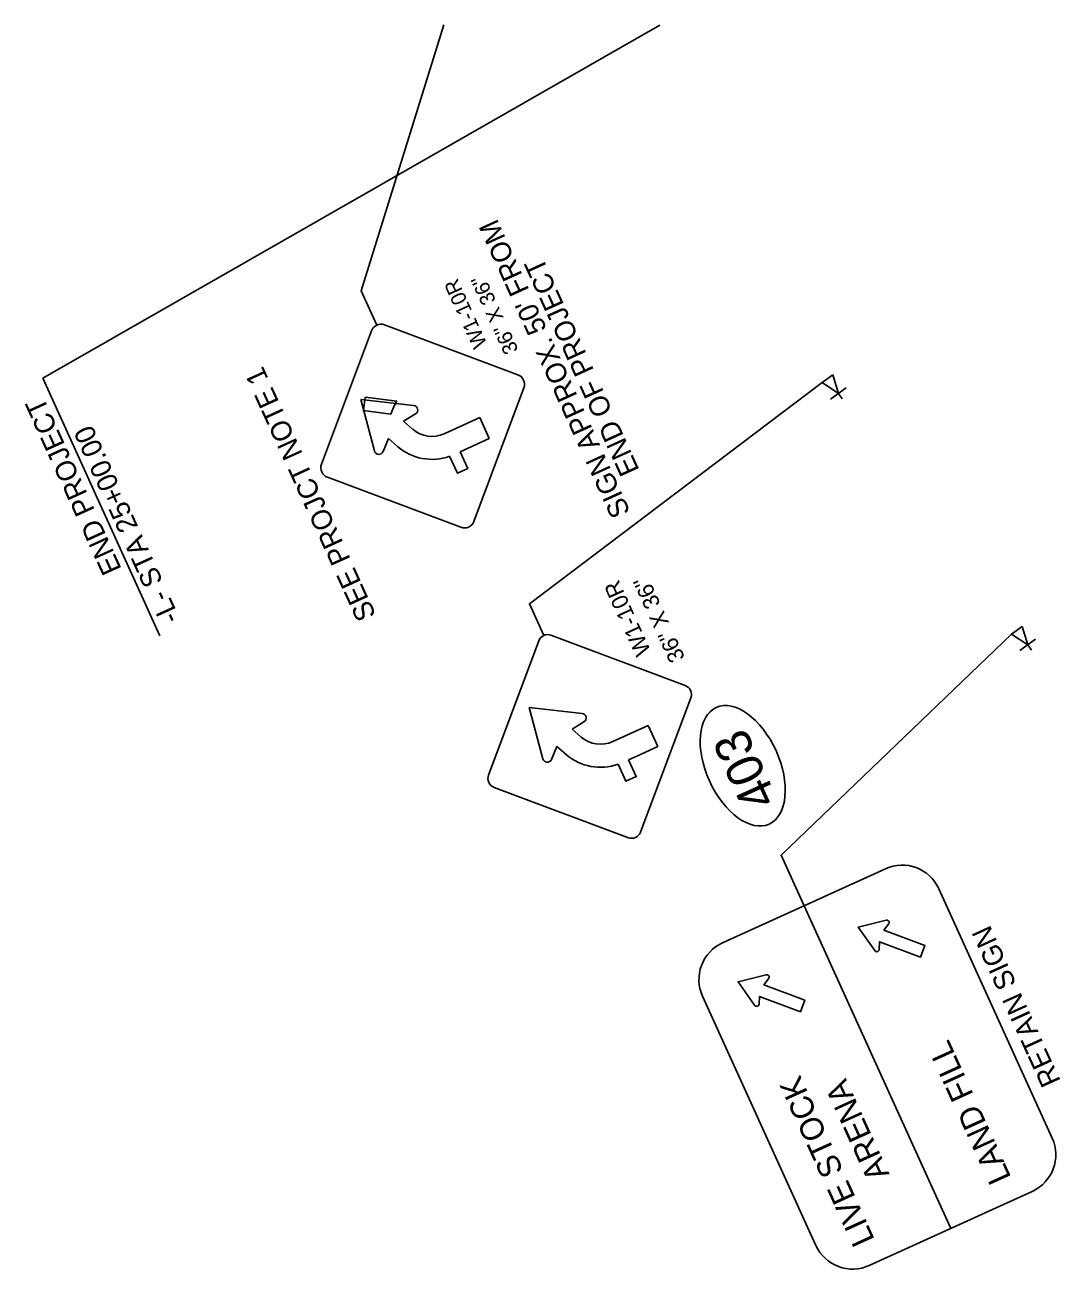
# Model space of a CAD drawing. Extents: x 2096093 to 2099001, y 683546 to 685907.
# Drawn here: x 2096092.8 to 2096451.4, y 684545 to 684975.9 of the extents above; entities that cross this region are included whole.
import ezdxf

# ---------------------------------------------------------------- set-up
doc = ezdxf.new("R2010")
doc.units = 0
for name, color, linetype in [('Default', 7, 'Continuous'), ('Exist Sign E Adopt a Highway CELL', 7, 'Continuous'), ('Exist Sign E Curve Left CELL', 7, 'Continuous'), ('Exist Sign F Left_Right Arrow CELL', 7, 'Continuous'), ('Prop DSN Text', 7, 'Continuous'), ('Prop Horizontal Alignment Station Label', 7, 'Continuous')]:
    doc.layers.add(name, color=color, linetype=linetype)

msp = doc.modelspace()

# ---------------------------------------------------------------- linework, layer by layer
at = {"layer": 'Default'}
for p, q in [((2096368.99, 684851.97), (2096372.7, 684854.63)), ((2096372.7, 684854.63), (2096374.61, 684848.25)), ((2096374.61, 684848.25), (2096368.99, 684851.97)), ((2096371.82, 684846.25), (2096377.35, 684850.22)), ((2096374.61, 684848.25), (2096375.96, 684846.37)), ((2096434.57, 684764.88), (2096438.28, 684767.54)), ((2096440.19, 684761.16), (2096434.57, 684764.88)), ((2096438.28, 684767.54), (2096440.19, 684761.16)), ((2096437.4, 684759.17), (2096442.93, 684763.13)), ((2096440.19, 684761.16), (2096441.54, 684759.28)), ((2096362.69, 684670.78), (2096354.72, 684688.29))]:
    msp.add_line(p, q, dxfattribs=at)
for points in [[(2096214.69, 684871.9), (2096209.27, 684883.81), (2096237.88, 684975.88)], [(2096272.53, 684764.39), (2096267.54, 684775.38), (2096368.99, 684851.97)], [(2096354.72, 684688.29), (2096354.72, 684688.29), (2096434.57, 684764.88)]]:
    msp.add_lwpolyline(points, dxfattribs=at)
msp.add_ellipse((2096341.46, 684719.27), major_axis=(9.17, -20.19), ratio=0.571429, dxfattribs=at)
at = {"layer": 'Exist Sign E Adopt a Highway CELL'}
msp.add_line((2096413.51, 684559.04), (2096362.69, 684670.78), dxfattribs=at)
for points in [[(2096334.45, 684657.94), (2096390.92, 684683.63)], [(2096409.37, 684676.71), (2096448.66, 684590.34)], [(2096366.83, 684553.12), (2096327.54, 684639.49)], [(2096441.74, 684571.89), (2096385.28, 684546.2)]]:
    msp.add_lwpolyline(points, dxfattribs=at)
for centre, start, end in [((2096396.69, 684670.95), 24.458, 114.458), ((2096340.22, 684645.26), 114.458, 204.458), ((2096435.98, 684584.57), 294.458, 24.458), ((2096379.51, 684558.88), 204.458, 294.458)]:
    msp.add_arc(centre, 13.93, start, end, dxfattribs=at)
at = {"layer": 'Exist Sign E Curve Left CELL'}
for p, q in [((2096263.59, 684854.68), (2096217.38, 684871.99)), ((2096212.85, 684869.93), (2096195.53, 684823.72)), ((2096248.33, 684803.93), (2096265.65, 684850.15)), ((2096209.11, 684846.15), (2096227.46, 684844.07)), ((2096213.86, 684828.32), (2096209.11, 684846.15)), ((2096227.46, 684844.07), (2096209.11, 684846.15)), ((2096209.11, 684846.15), (2096213.86, 684828.32)), ((2096227.46, 684844.07), (2096209.11, 684846.15)), ((2096209.11, 684846.15), (2096213.86, 684828.32)), ((2096228.11, 684841.13), (2096223.96, 684838.61)), ((2096223.96, 684838.61), (2096228.11, 684841.13)), ((2096223.96, 684838.61), (2096228.11, 684841.13)), ((2096223.96, 684838.61), (2096227.12, 684835.86)), ((2096227.12, 684835.86), (2096223.96, 684838.61)), ((2096227.12, 684835.86), (2096223.96, 684838.61)), ((2096238.08, 684834.29), (2096250.35, 684839.88)), ((2096250.35, 684839.88), (2096238.08, 684834.29)), ((2096250.35, 684839.88), (2096238.08, 684834.29)), ((2096250.35, 684839.88), (2096253.65, 684832.62)), ((2096253.65, 684832.62), (2096250.35, 684839.88)), ((2096253.65, 684832.62), (2096250.35, 684839.88)), ((2096216.85, 684828.1), (2096218.75, 684832.58)), ((2096218.75, 684832.58), (2096221.91, 684829.83)), ((2096246.37, 684829.3), (2096243.54, 684828.02)), ((2096243.54, 684828.02), (2096246.37, 684829.3)), ((2096243.54, 684828.02), (2096246.37, 684829.3)), ((2096253.65, 684832.62), (2096246.37, 684829.3)), ((2096246.37, 684829.3), (2096253.65, 684832.62)), ((2096246.37, 684829.3), (2096253.65, 684832.62)), ((2096213.86, 684828.32), (2096213.85, 684828.31)), ((2096213.86, 684828.32), (2096213.85, 684828.31)), ((2096197.59, 684819.19), (2096243.81, 684801.87))]:
    msp.add_line(p, q, dxfattribs=at)
for points in [[(2096221.67, 684845.56), (2096210.61, 684846.94), (2096210.04, 684842.28), (2096219.56, 684841.09)], [(2096221.91, 684829.83), (2096218.75, 684832.58), (2096216.85, 684828.1)], [(2096216.85, 684828.1), (2096218.75, 684832.58), (2096221.91, 684829.83)], [(2096239.93, 684826.45), (2096242.61, 684820.57), (2096246.18, 684822.2), (2096243.54, 684828.02)], [(2096239.93, 684826.45), (2096242.61, 684820.57), (2096246.18, 684822.2), (2096243.54, 684828.02)], [(2096239.93, 684826.45), (2096242.61, 684820.57), (2096246.18, 684822.2), (2096243.54, 684828.02)]]:
    msp.add_lwpolyline(points, dxfattribs=at)
for centre, radius, start, end in [((2096216.14, 684868.7), 3.52, 69.458, 159.458), ((2096262.36, 684851.38), 3.52, 339.458, 69.458), ((2096237.44, 684835.39), 18.77, 147.1671, 162.2946), ((2096227.28, 684842.49), 1.59, 301.3774, 83.5059), ((2096227.28, 684842.49), 1.59, 301.3774, 83.5059), ((2096227.28, 684842.49), 1.59, 301.3774, 83.5059), ((2096233.83, 684843.63), 10.26, 229.1817, 294.4888), ((2096233.83, 684843.63), 10.26, 229.1817, 294.4888), ((2096233.83, 684843.63), 10.26, 229.1817, 294.4888), ((2096233.83, 684843.63), 18.23, 229.1817, 289.562), ((2096233.83, 684843.63), 18.23, 229.1817, 289.562), ((2096233.83, 684843.63), 18.23, 229.1817, 289.562), ((2096215.39, 684828.72), 1.59, 194.8575, 336.9795), ((2096215.39, 684828.72), 1.59, 194.8575, 336.9795), ((2096215.39, 684828.72), 1.59, 194.8575, 336.9795), ((2096198.83, 684822.48), 3.52, 159.458, 249.458), ((2096245.04, 684805.17), 3.52, 249.458, 339.458)]:
    msp.add_arc(centre, radius, start, end, dxfattribs=at)
at = {"layer": 'Exist Sign F Left_Right Arrow CELL'}
for points in [[(2096387.18, 684655.25), (2096381.47, 684663.4), (2096391.13, 684665.79)], [(2096387.18, 684655.25), (2096381.47, 684663.4), (2096391.13, 684665.79)], [(2096387.18, 684655.25), (2096381.47, 684663.4), (2096391.13, 684665.79)], [(2096392.01, 684664.43), (2096390.37, 684662.35), (2096404.55, 684657.03), (2096403.05, 684653.03), (2096388.87, 684658.34), (2096388.74, 684655.7)], [(2096392.01, 684664.43), (2096390.37, 684662.35), (2096404.55, 684657.03), (2096403.05, 684653.03), (2096388.87, 684658.34), (2096388.74, 684655.7)], [(2096392.01, 684664.43), (2096390.37, 684662.35), (2096404.55, 684657.03), (2096403.05, 684653.03), (2096388.87, 684658.34), (2096388.74, 684655.7)], [(2096345.58, 684636.33), (2096339.88, 684644.48), (2096349.53, 684646.87)], [(2096345.58, 684636.33), (2096339.88, 684644.48), (2096349.53, 684646.87)], [(2096345.58, 684636.33), (2096339.88, 684644.48), (2096349.53, 684646.87)], [(2096350.41, 684645.51), (2096348.78, 684643.43), (2096362.95, 684638.11), (2096361.45, 684634.11), (2096347.28, 684639.42), (2096347.14, 684636.78)], [(2096350.41, 684645.51), (2096348.78, 684643.43), (2096362.95, 684638.11), (2096361.45, 684634.11), (2096347.28, 684639.42), (2096347.14, 684636.78)], [(2096350.41, 684645.51), (2096348.78, 684643.43), (2096362.95, 684638.11), (2096361.45, 684634.11), (2096347.28, 684639.42), (2096347.14, 684636.78)]]:
    msp.add_lwpolyline(points, dxfattribs=at)
for centre, start, end in [((2096391.34, 684664.96), 321.857, 103.9072), ((2096391.34, 684664.96), 321.857, 103.9072), ((2096391.34, 684664.96), 321.857, 103.9072), ((2096387.88, 684655.74), 215.0087, 357.0589), ((2096387.88, 684655.74), 215.0087, 357.0589), ((2096387.88, 684655.74), 215.0087, 357.0589), ((2096349.74, 684646.04), 321.857, 103.9072), ((2096349.74, 684646.04), 321.857, 103.9072), ((2096349.74, 684646.04), 321.857, 103.9072), ((2096346.29, 684636.82), 215.0087, 357.0589), ((2096346.29, 684636.82), 215.0087, 357.0589), ((2096346.29, 684636.82), 215.0087, 357.0589)]:
    msp.add_arc(centre, 0.856, start, end, dxfattribs=at)
at = {"layer": 'Prop DSN Text'}
for p, q in [((2096227.97, 684833.86), (2096227.95, 684833.84)), ((2096213.85, 684828.31), (2096213.86, 684828.32)), ((2096321.57, 684747.04), (2096275.04, 684764.48)), ((2096272.22, 684721.67), (2096267.48, 684739.51)), ((2096267.48, 684739.51), (2096285.82, 684737.43)), ((2096285.82, 684737.43), (2096267.48, 684739.51)), ((2096267.48, 684739.51), (2096272.22, 684721.67)), ((2096286.47, 684734.49), (2096282.32, 684731.97)), ((2096282.32, 684731.97), (2096286.47, 684734.49)), ((2096282.32, 684731.97), (2096285.48, 684729.22)), ((2096285.48, 684729.22), (2096282.32, 684731.97)), ((2096296.44, 684727.65), (2096308.71, 684733.24)), ((2096308.71, 684733.24), (2096296.44, 684727.65)), ((2096308.71, 684733.24), (2096312.01, 684725.98)), ((2096312.01, 684725.98), (2096308.71, 684733.24)), ((2096286.33, 684727.22), (2096286.31, 684727.2)), ((2096312.01, 684725.98), (2096304.73, 684722.66)), ((2096304.73, 684722.66), (2096312.01, 684725.98)), ((2096272.21, 684721.67), (2096272.22, 684721.67)), ((2096272.22, 684721.67), (2096272.21, 684721.67)), ((2096304.73, 684722.66), (2096301.9, 684721.37)), ((2096301.9, 684721.37), (2096304.73, 684722.66))]:
    msp.add_line(p, q, dxfattribs=at)
for points in [[(2096270.82, 684762.56), (2096253.38, 684716.03)], [(2096306.06, 684696.29), (2096323.49, 684742.82)], [(2096280.27, 684723.19), (2096277.11, 684725.94), (2096275.21, 684721.45)], [(2096275.21, 684721.45), (2096277.11, 684725.94), (2096280.27, 684723.19)], [(2096298.3, 684719.8), (2096300.97, 684713.93), (2096304.55, 684715.56), (2096301.9, 684721.37)], [(2096298.3, 684719.8), (2096300.97, 684713.93), (2096304.55, 684715.56), (2096301.9, 684721.37)], [(2096255.31, 684711.81), (2096301.84, 684694.37)]]:
    msp.add_lwpolyline(points, dxfattribs=at)
for centre, radius, start, end in [((2096273.89, 684761.41), 3.28, 69.458, 159.458), ((2096320.42, 684743.97), 3.28, 24.458, 69.458), ((2096320.42, 684743.97), 3.28, 339.458, 24.458), ((2096285.64, 684735.85), 1.59, 301.3774, 83.5059), ((2096285.64, 684735.85), 1.59, 301.3774, 83.5059), ((2096292.19, 684736.98), 10.26, 229.1817, 294.4888), ((2096292.19, 684736.98), 10.26, 229.1817, 294.4888), ((2096273.75, 684722.08), 1.59, 194.8575, 336.9795), ((2096273.75, 684722.08), 1.59, 194.8575, 336.9795), ((2096292.19, 684736.98), 18.23, 229.1817, 289.562), ((2096292.19, 684736.98), 18.23, 229.1817, 289.562), ((2096256.46, 684714.88), 3.28, 159.445, 204.4515), ((2096256.46, 684714.88), 3.28, 204.4515, 249.458), ((2096302.99, 684697.44), 3.28, 249.458, 339.458)]:
    msp.add_arc(centre, radius, start, end, dxfattribs=at)
at = {"layer": 'Prop Horizontal Alignment Station Label'}
for p in [(2096312.78, 684975.81), (2096139.58, 684764.33)]:
    msp.add_line(p, (2096099, 684853.56), dxfattribs=at)

# ---------------------------------------------------------------- texts
at = {"layer": 'Default'}
for s, height, rotation, p in [("SIGN APPROX. 50' FROM", 7, 114.4888, (2096302.65, 684807.11)), ('END OF PROJECT', 7, 114.4888, (2096305.77, 684821.67)), ('SEE PROJCT NOTE 1', 7, 114.4888, (2096214.58, 684771.38)), ('403', 12.516, 114.4239, (2096353.66, 684707.54)), ('RETAIN SIGN', 7, 114.4888, (2096451.73, 684610.07))]:
    msp.add_text(s, height=height, rotation=rotation, dxfattribs=at).set_placement(p)
at = {"layer": 'Exist Sign E Adopt a Highway CELL'}
for s, p in [('LAND FILL', (2096434.59, 684576.64)), ('LIVE STOCK', (2096387.31, 684555.13)), ('ARENA', (2096392.37, 684577.8))]:
    msp.add_text(s, height=8, rotation=114.458, dxfattribs=at).set_placement(p)
at = {"layer": 'Prop DSN Text'}
for s, height, p in [('W1-10R', 5.174, (2096253.02, 684865.33)), ("36'' X 36''", 5.1742, (2096263.86, 684863.23)), ('W1-10R', 5.625, (2096309.78, 684758.92)), ("36'' X 36''", 5.6251, (2096321.56, 684756.63))]:
    msp.add_text(s, height=height, rotation=114.458, dxfattribs=at).set_placement(p)
at = {"layer": 'Prop Horizontal Alignment Station Label'}
for s, p in [('END PROJECT', (2096126.41, 684787.4)), ('-L- STA 25+00.00', (2096146.57, 684770.31))]:
    msp.add_text(s, height=7, rotation=114.458, dxfattribs=at).set_placement(p)

doc.saveas('drawing.dxf')
